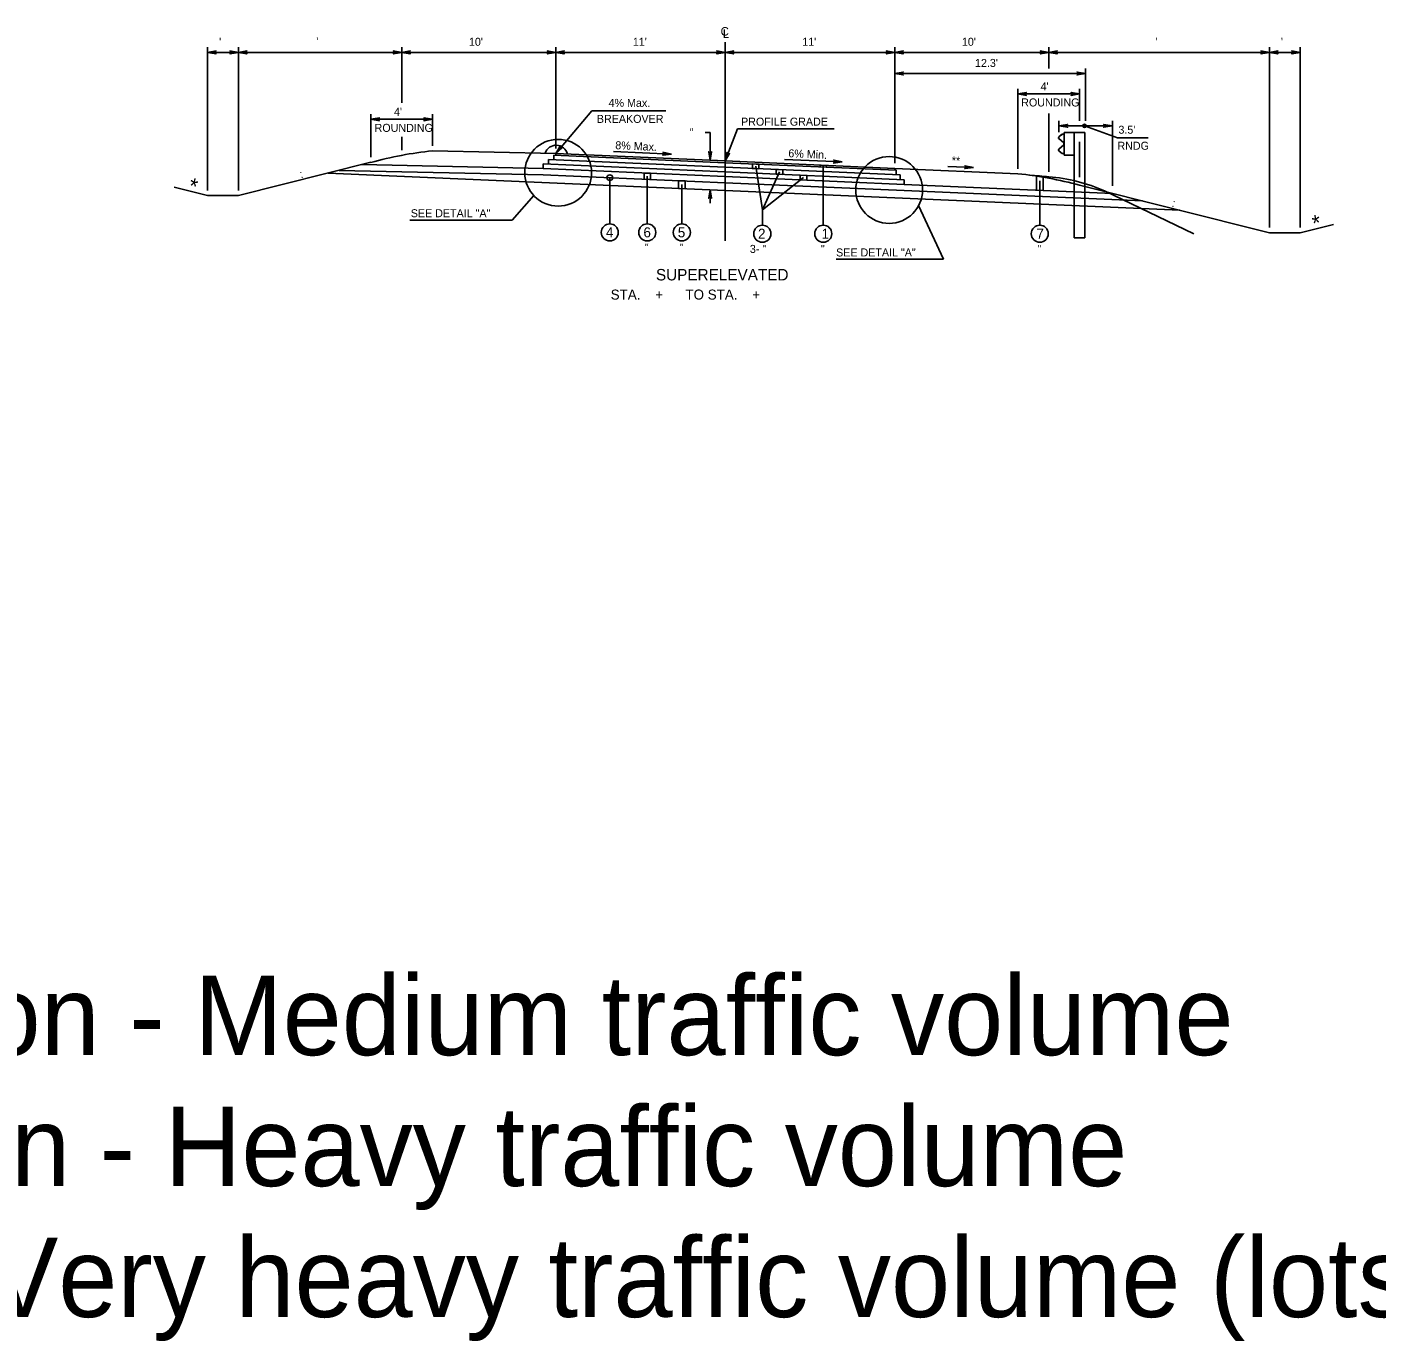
# Model space of a CAD drawing. Extents: x -540 to 1231, y -564 to 421.
# Drawn here: x 724.3 to 960.2, y -487.6 to -257.9 of the extents above; entities that cross this region are included whole.
import ezdxf

# ---------------------------------------------------------------- set-up
doc = ezdxf.new("R2010")
doc.units = 0
doc.layers.add('1', color=7, linetype='Continuous')
doc.layers.add('Des_ Drain_ Ftrs', color=7, linetype='Continuous')

msp = doc.modelspace()

# ---------------------------------------------------------------- linework, layer by layer
at = {"layer": '1'}
for p, q in [((755.88, -286.44), (755.88, -261.41)), ((761.27, -286.44), (761.27, -261.41)), ((789.84, -271.11), (789.84, -261.41)), ((816.78, -279.1), (816.78, -261.41)), ((846.41, -295.25), (846.41, -260.53)), ((876.05, -281.69), (876.05, -261.41)), ((902.99, -265.11), (902.99, -261.41)), ((941.57, -292.94), (941.57, -261.41)), ((946.96, -292.94), (946.96, -261.41)), ((761.27, -262.29), (755.88, -262.29)), ((789.84, -262.29), (761.27, -262.29)), ((816.78, -262.29), (789.84, -262.29)), ((846.41, -262.29), (816.78, -262.29)), ((846.41, -262.29), (876.05, -262.29)), ((876.05, -262.29), (902.99, -262.29)), ((902.99, -262.29), (941.57, -262.29)), ((941.57, -262.29), (946.96, -262.29)), ((876.05, -265.99), (909.42, -265.99)), ((909.42, -274.27), (909.42, -265.11)), ((897.6, -282.64), (897.6, -268.68)), ((908.38, -274.27), (908.38, -268.68)), ((897.6, -269.56), (908.38, -269.56)), ((784.45, -280.64), (784.45, -273.12)), ((795.22, -278.63), (795.22, -273.12)), ((816.77, -279.98), (823.1, -272.52)), ((836.04, -272.52), (823.1, -272.52)), ((902.99, -283.17), (902.99, -272.97)), ((795.22, -274), (784.45, -274)), ((846.41, -281.28), (848.56, -275.69)), ((865.48, -275.69), (848.56, -275.69)), ((904.73, -276.22), (904.73, -274.27)), ((904.73, -275.15), (914.11, -275.15)), ((909.24, -275.15), (915.01, -277.22)), ((914.11, -285.63), (914.11, -274.27)), ((789.84, -279.41), (789.84, -277.06)), ((843.78, -276.28), (842.9, -276.28)), ((843.78, -276.28), (843.78, -281.16)), ((904.79, -277.43), (905.55, -278.07)), ((905.35, -276.61), (904.81, -277)), ((904.81, -277.41), (905.57, -278.05)), ((905.36, -276.64), (904.83, -277.03)), ((905.67, -276.56), (905.35, -276.61)), ((905.67, -276.59), (905.36, -276.64)), ((905.64, -278.26), (905.64, -278.33)), ((905.67, -276.33), (905.67, -280.26)), ((905.67, -276.33), (907.42, -276.33)), ((905.67, -278.26), (905.67, -278.33)), ((907.42, -276.33), (907.42, -294.73)), ((909.31, -276.33), (907.42, -276.33)), ((908.38, -284.09), (908.38, -277.94)), ((909.31, -276.33), (909.31, -294.73)), ((915.01, -277.22), (920.35, -277.22)), ((795.22, -279.51), (816.77, -279.98)), ((846.41, -281.58), (816.43, -280.27)), ((816.43, -281.08), (816.43, -280.27)), ((846.41, -281.28), (816.77, -279.98)), ((816.77, -279.98), (816.77, -280.28)), ((826.87, -279.63), (836.99, -280.07)), ((905.55, -278.52), (904.79, -279.16)), ((905.57, -278.54), (904.81, -279.18)), ((904.81, -279.59), (905.35, -279.98)), ((904.83, -279.56), (905.36, -279.95)), ((905.35, -279.98), (905.67, -280.03)), ((905.36, -279.95), (905.67, -280)), ((905.67, -280.26), (907.42, -280.26)), ((784.45, -281.52), (761.27, -287.32)), ((778.89, -282.92), (814.59, -283.69)), ((782.85, -281.92), (814.59, -282.62)), ((846.41, -283.2), (814.59, -281.81)), ((814.59, -282.62), (814.59, -281.81)), ((846.41, -284.01), (814.59, -282.62)), ((846.41, -282.39), (815.51, -281.04)), ((815.51, -281.85), (815.51, -281.04)), ((876.05, -282.57), (846.41, -281.28)), ((876.29, -282.88), (846.41, -281.58)), ((876.99, -283.72), (846.41, -282.39)), ((851.74, -282.21), (852.9, -289.83)), ((856.75, -281.01), (866.86, -281.46)), ((863.56, -282.19), (863.56, -292.52)), ((897.6, -283.52), (876.05, -282.57)), ((876.05, -282.57), (876.05, -282.87)), ((876.29, -282.88), (876.29, -283.69)), ((889.81, -282.43), (885.31, -282.23)), ((846.41, -286.43), (776.95, -283.4)), ((846.41, -285.08), (814.59, -283.69)), ((826.22, -284.2), (826.22, -292.28)), ((832.78, -283.95), (832.78, -292.28)), ((838.82, -285.42), (838.82, -292.28)), ((877.69, -284.56), (846.41, -283.2)), ((877.69, -285.37), (846.41, -284.01)), ((877.69, -286.45), (846.41, -285.08)), ((855.91, -283.19), (852.9, -289.83)), ((860.09, -284.2), (852.9, -289.83)), ((876.99, -283.72), (876.99, -284.53)), ((877.69, -284.56), (877.69, -285.37)), ((914.13, -286.96), (877.69, -285.37)), ((901.42, -284.73), (901.42, -292.52)), ((904.73, -284.28), (904.73, -284.28)), ((750.05, -285.86), (755.88, -287.32)), ((761.27, -287.32), (755.88, -287.32)), ((809.17, -291.62), (812.91, -287.3)), ((843.78, -286.32), (843.78, -288.68)), ((925.89, -289.9), (846.41, -286.43)), ((919.36, -288.27), (877.69, -286.45)), ((908.38, -285.52), (941.57, -293.82)), ((912.73, -286.51), (928.34, -294.03)), ((852.9, -289.83), (852.9, -292.52)), ((880.22, -289.09), (884.58, -298.48)), ((791.23, -291.62), (809.17, -291.62)), ((952.79, -292.37), (946.96, -293.82)), ((909.31, -294.73), (907.42, -294.73)), ((941.57, -293.82), (946.96, -293.82)), ((865.79, -298.48), (884.58, -298.48))]:
    msp.add_line(p, q, dxfattribs=at)
for points in [[(851.16, -281.79), (852.31, -281.84), (852.31, -282.65), (851.16, -282.6)], [(855.34, -282.78), (856.49, -282.83), (856.49, -283.64), (855.34, -283.59)], [(862.99, -282), (864.14, -282.05), (864.14, -282.35), (862.99, -282.3)], [(832.21, -283.39), (833.35, -283.44), (833.35, -284.51), (832.21, -284.46)], [(838.24, -284.73), (839.39, -284.78), (839.39, -286.13), (838.24, -286.08)], [(859.52, -283.77), (860.66, -283.82), (860.66, -284.63), (859.52, -284.58)], [(900.84, -283.93), (901.99, -284.11), (901.99, -286.43), (900.84, -286.38)]]:
    msp.add_lwpolyline(points, close=True, dxfattribs=at)
for centre, radius in [((817.2, -283.34), 5.84), ((875.07, -286.35), 5.84), ((826.22, -284.2), 0.5), ((826.22, -293.77), 1.49), ((832.78, -293.77), 1.49), ((838.82, -293.77), 1.49), ((852.9, -294), 1.49), ((863.56, -294), 1.49), ((901.42, -294), 1.49)]:
    msp.add_circle(centre, radius, dxfattribs=at)
for centre, radius, start, end in [((802.12, -346.35), 67.19, 95.8911, 105.2497), ((816.85, -280.52), 2, 12.9578, 163.1849), ((890.71, -350.35), 67.19, 74.7602, 84.1188)]:
    msp.add_arc(centre, radius, start, end, dxfattribs=at)
msp.add_ellipse((909.24, -275.15), major_axis=(-0.311, 0), ratio=0.964041, dxfattribs=at)
for centre, major_axis, start_param, end_param in [((904.98, -277.22), (-0.288, 0), 5.35781, 7.138763), ((904.98, -277.22), (-0.258, 0), 5.35781, 7.138763), ((905.38, -278.26), (0.258, 0), 0, 0.855848), ((905.38, -278.33), (0.258, 0), 5.427337, 6.283185), ((905.38, -278.26), (0.288, 0), 0, 0.855848), ((905.38, -278.33), (0.288, 0), 5.427337, 6.283185), ((904.98, -279.37), (-0.288, 0), 5.427608, 7.208561), ((904.98, -279.37), (-0.258, 0), 5.427608, 7.208561), ((891.77, -384.72), (105.02, 0), 1.463691, 1.495354), ((900.79, -311.34), (28.39, 0), 1.136862, 1.493152)]:
    msp.add_ellipse(centre, major_axis=major_axis, ratio=0.964041, start_param=start_param, end_param=end_param, dxfattribs=at)
at = {"layer": 'Des_ Drain_ Ftrs'}
for points in [[(755.88, -262.29), (757.37, -262.54), (757.07, -262.29), (757.37, -262.04)], [(761.27, -262.29), (759.78, -262.54), (760.07, -262.29), (759.78, -262.04)], [(761.27, -262.29), (762.75, -262.54), (762.46, -262.29), (762.75, -262.04)], [(789.84, -262.29), (788.35, -262.54), (788.64, -262.29), (788.35, -262.04)], [(789.84, -262.29), (791.32, -262.54), (791.03, -262.29), (791.32, -262.04)], [(816.78, -262.29), (815.29, -262.54), (815.58, -262.29), (815.29, -262.04)], [(816.78, -262.29), (818.26, -262.54), (817.97, -262.29), (818.26, -262.04)], [(846.41, -262.29), (844.92, -262.54), (845.22, -262.29), (844.92, -262.04)], [(846.41, -262.29), (847.9, -262.54), (847.6, -262.29), (847.9, -262.04)], [(876.05, -262.29), (874.56, -262.54), (874.85, -262.29), (874.56, -262.04)], [(876.05, -262.29), (877.53, -262.54), (877.24, -262.29), (877.53, -262.04)], [(902.99, -262.29), (901.5, -262.54), (901.79, -262.29), (901.5, -262.04)], [(902.99, -262.29), (904.48, -262.54), (904.18, -262.29), (904.48, -262.04)], [(941.57, -262.29), (940.09, -262.54), (940.38, -262.29), (940.09, -262.04)], [(941.57, -262.29), (943.06, -262.54), (942.77, -262.29), (943.06, -262.04)], [(946.96, -262.29), (945.47, -262.54), (945.77, -262.29), (945.47, -262.04)], [(876.05, -265.99), (877.54, -266.24), (877.24, -265.99), (877.54, -265.74)], [(909.42, -265.99), (907.93, -266.24), (908.22, -265.99), (907.93, -265.74)], [(897.6, -269.56), (899.09, -269.81), (898.79, -269.56), (899.09, -269.31)], [(908.38, -269.56), (906.89, -269.81), (907.18, -269.56), (906.89, -269.31)], [(784.45, -274), (785.94, -274.25), (785.64, -274), (785.94, -273.76)], [(795.22, -274), (793.73, -274.25), (794.03, -274), (793.73, -273.76)], [(904.73, -275.15), (906.27, -275.39), (905.96, -275.15), (906.27, -274.9)], [(914.11, -275.15), (912.57, -275.39), (912.87, -275.15), (912.57, -274.9)], [(816.77, -279.98), (817.92, -279.01), (817.54, -279.07), (817.54, -278.69)], [(836.99, -280.07), (835.49, -280.25), (835.8, -280.02), (835.51, -279.76)], [(843.78, -281.16), (844.03, -279.68), (843.78, -279.97), (843.54, -279.68)], [(846.41, -281.28), (847.18, -279.98), (846.84, -280.16), (846.71, -279.8)], [(866.86, -281.46), (865.37, -281.64), (865.67, -281.4), (865.39, -281.14)], [(889.81, -282.43), (888.31, -282.61), (888.62, -282.38), (888.33, -282.12)], [(843.78, -286.32), (844.03, -287.8), (843.78, -287.51), (843.54, -287.8)]]:
    msp.add_lwpolyline(points, close=True, dxfattribs=at)

# ---------------------------------------------------------------- texts
at = {"layer": '1'}
for s, height, p in [(" '", 1.4, (757.38, -261.14)), ("  '", 1.4, (773.85, -261.06)), ("10'", 1.4, (801.59, -261.14)), ("11'", 1.4, (830.25, -261.14)), ("11'", 1.4, (859.88, -261.14)), ("10'", 1.4, (887.8, -261.14)), ("  '", 1.4, (920.59, -261.14)), (" '", 1.4, (943.07, -261.14)), ("12.3'", 1.4, (890.09, -264.84)), ("4'", 1.4, (901.56, -268.95)), ('4% Max.', 1.4, (826.01, -271.82)), ('ROUNDING', 1.4, (898.17, -271.75)), ("4'", 1.4, (788.48, -273.39)), ('BREAKOVER', 1.4, (823.96, -274.62)), ('ROUNDING', 1.4, (785.09, -276.19)), ('PROFILE GRADE', 1.4, (849.18, -275.11)), ("3.5'", 1.4, (915.17, -276.52)), ('RNDG', 1.4, (915, -279.32)), ('SEE DETAIL "A"', 1.4, (791.42, -291.12)), ('4', 1.75, (825.54, -294.64)), ('6', 1.75, (832.11, -294.64)), ('5', 1.75, (838.12, -294.64)), ('2', 1.75, (852.15, -294.88)), ('1', 1.75, (863.26, -294.88)), ('7', 1.75, (900.83, -294.88)), (' "', 1.4, (831.83, -297.13)), (' "', 1.4, (837.87, -297.13)), ('3- "', 1.4, (850.72, -297.36)), (' "', 1.4, (862.62, -297.36)), ('SEE DETAIL "A"', 1.4, (865.8, -297.98)), ('  "', 1.4, (899.97, -297.36)), ('SUPERELEVATED', 2, (834.29, -302.17)), ('STA.    +      TO STA.    +     ', 1.75, (826.38, -305.52)), ('1)  0.3 to <3 million - Medium traffic volume', 13.8978, (579.49, -437.65)), ('2)  3 to <30 million - Heavy traffic volume', 13.8978, (579.49, -460.55)), ('3)  > 30 million - Very heavy traffic volume (lots of trucks)', 13.8978, (579.49, -483.45))]:
    msp.add_text(s, height=height, dxfattribs=at).set_placement(p)
for s, height, rotation, p in [('  "', 1.4, 0.1438, (839.17, -276.99)), ('8% Max.', 1.4, 357.3762, (827.16, -279.21)), ('6% Min.', 1.4, 357.376, (857.42, -280.62)), ('**', 1.4, 357.2166, (885.99, -281.87)), ('*', 2.8, 347.1521, (752.36, -286.89)), (' : ', 1.4, 14.2282, (771.68, -284.44)), (' : ', 1.4, 345.7718, (923.93, -289.12)), ('*', 2.8, 12.8479, (949.42, -293.63))]:
    msp.add_text(s, height=height, rotation=rotation, dxfattribs=at).set_placement(p)
at = {"layer": 'Des_ Drain_ Ftrs'}
for s, p in [('C', (845.6, -259.37)), ('L', (845.99, -259.77))]:
    msp.add_text(s, height=1.5, dxfattribs=at).set_placement(p)

doc.saveas('drawing.dxf')
